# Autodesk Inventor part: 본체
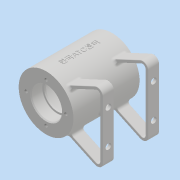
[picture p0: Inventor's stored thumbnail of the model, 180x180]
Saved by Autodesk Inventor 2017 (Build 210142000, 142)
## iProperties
Part Number: 본체
Material: 일반
Document SubType Name: Modeling
Designer: Administrator
Density: 1 g/cm^3
Appearance: 기본값
Author: Administrator
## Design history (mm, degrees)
sketch "스케치1"
  geometry: C1 r 29 at (0, 0); 1 further point
  constraints: 1 centre point, 1 coincident
  dimensions: "d0" = 58 diameter of C1
extrude "돌출1" new body sketch "스케치1" distance "d1" = 35; taper "d3" = 0 deg; dims "d2" = 35, "d4" = 0
sketch "스케치2"
  geometry: C1 r 21 at (0, 0); 1 further point
  constraints: 1 centre point, 1 coincident
  dimensions: "d5" = 42 diameter of C1
extrude "돌출2" cut sketch "스케치2" distance "d6" = 21; taper "d8" = 0 deg; dims "d7" = 21, "d9" = 0
sketch "스케치3"
  geometry: C1 r 14 at (0, 0); 1 further point
  constraints: 1 centre point, 1 coincident
  dimensions: "d10" = 28 diameter of C1
extrude "돌출3" cut sketch "스케치3" distance "d11" = 23; taper "d13" = 0 deg; dims "d12" = 23, "d14" = 0
sketch "스케치4"
  geometry: C1 r 14 at (0, 0) reference; C2 r 16 at (0, 0); 1 further point
  constraints: 1 centre point, 1 coincident
  dimensions: "d15" = 32 diameter of C2
extrude "돌출4" cut sketch "스케치4" distance "d16" = 12; taper "d17" = 0 deg
sketch "스케치5"
  geometry: C1 r 16 at (0, 0); 1 further point
  constraints: 1 centre point, 1 coincident
  dimensions: "d18" = 32 diameter of C1
extrude "돌출5" cut sketch "스케치5" distance "d19" = 12; taper "d20" = 0 deg
sketch "스케치6"
  geometry: 2 further points
  constraints: 1 horizontal alignment
  dimensions: "d21" = 21 distance of point (0, 0) point (-21, 0)
hole "구멍1" sketch "스케치6" at (-21, 0) diameter "d22" = 3.242; stored, may be unused: countersink angle "d26" = 90 deg, drill point angle "d28" = 118 deg; dims "d23" = 8, "d24" = 4, "d25" = 2, "d27" = 10
sketch "스케치7"
  geometry: 2 further points
  constraints: 1 horizontal alignment
  dimensions: "d32" = 21 distance of point (0, 0) point (-21, 0)
hole "구멍2" sketch "스케치7" at (-21, 0) diameter "d33" = 3.242; stored, may be unused: countersink angle "d37" = 90 deg, drill point angle "d39" = 118 deg; dims "d34" = 8, "d35" = 4, "d36" = 2, "d38" = 10
sketch "스케치8"
  geometry: L1 (0, 0)-(-30.07, -10.945); L2 (0, 0)-(32, 0); L3 (-30.07, -10.945)-(-28.018, -16.583); L4 (-23.397, -8.516)-(-21.345, -14.154); L5 (-21.345, -14.154)-(-28.018, -16.583)
  constraints: 10 end point, 2 perpendicular, 1 equal length, 1 horizontal, 1 parallel, 1 point on line
  dimensions: "d43" = 160 deg angle of L1 L2; "d45" = 32 distance of L1.start L1.end; "d46" = 6 distance of L1.end L3.end; "d47" = 6.67327 horizontal distance of L4.end L3.end
revolve "회전1" sketch "스케치8" stored, may be unused: angle "d48" = 90 deg
sketch "스케치9"
  geometry: 2 further points
  constraints: 2 coincident
hole "구멍3" sketch "스케치9" at (0, 0) diameter "d49" = 5.188; stored, may be unused: countersink angle "d53" = 90 deg, drill point angle "d55" = 118 deg; dims "d50" = 20, "d51" = 4, "d52" = 2, "d54" = 29
node "작업 평면1"
sketch "스케치12"
  geometry: C1 r 5 at (0, 0); 1 further point
  constraints: 1 centre point, 1 coincident
  dimensions: "d59" = 10 diameter of C1
extrude "돌출6" join sketch "스케치12" stored distance "d60" = 10; taper "d61" = 0 deg
node "작업 평면2"
sketch "스케치13"
  geometry: L1 (-55, 30.582)-(-55, -30.582); L2 (0, 0)-(0, -50.41); L3 (-46.464, -36.02)-(-17.993, -22.743); L4 (-55, -40)-(-23.585, -40); L5 (-46.464, 36.02)-(-17.993, 22.743); L6 (-55, 40)-(-23.585, 40); L7 (-20.438, 20.574)-(-47.732, 33.301); L8 (-52, 30.582)-(-52, -30.582); L9 (-47.732, -33.301)-(-20.438, -20.574); A1 r 29 centre (0, 0) between (-17.993, 22.743) and (-17.993, -22.743) reference; A2 r 6 centre (-49, -30.582) between (-55, -30.582) and (-46.464, -36.02); A3 r 6 centre (-49, 30.582) between (-46.464, 36.02) and (-55, 30.582); A4 r 3 centre (-49, 30.582) between (-47.732, 33.301) and (-52, 30.582); A5 r 3 centre (-49, -30.582) between (-52, -30.582) and (-47.732, -33.301); 2 further points
  constraints: 18 end point, 12 point on circle, 4 centre point, 4 point on line, 4 tangent, 2 equal length, 2 horizontal, 1 equal radius, 1 horizontal alignment, 1 midpoint, 1 parallel, 1 vertical, 2 other
  dimensions: "d63" = 55 distance from line of L1 point (0, 0); "d64" = 80 distance of L6.start L4.start; "d65" = 25 deg angle of L4 L3; "d66" = 25 deg angle of L5 L6; "d67" = 50.40972 distance of L2.start L2.end; "d71" = 6 radius of A2; "d72" = 3 distance between parallel lines of L5 L7; "d73" = 3 distance between parallel lines of L1 L8; "d74" = 3 distance between parallel lines of L3 L9
extrude "돌출7" join sketch "스케치13" distance "d75" = 12; taper "d76" = 0 deg
sketch "스케치14"
  geometry: L1 (0, 0)-(61.164, 0) reference; L2 (61.164, 0)-(61.164, 12) reference; L3 (0, 12)-(61.164, 12) reference; L4 (0, 0)-(0, 12) reference; C1 r 3 at (48.582, 6); C2 r 3 at (12.582, 6); 1 further point
  constraints: 2 centre point
  dimensions: "d77" = 6 diameter of C1; "d78" = 6 diameter of C2; "d80" = 6 distance from line of L3 C1.centre; "d81" = 6 distance from line of L3 C2.centre; "d82" = 36 distance of C2.centre C1.centre; "d83" = 18 horizontal distance of point (30.582, -18) C1.centre
extrude "돌출8" cut sketch "스케치14" distance "d84" = 12; taper "d85" = 0 deg
sketch "스케치15"
  geometry: 2 further points
  constraints: 1 coincident
hole "구멍4" sketch "스케치15" at (0, 0) diameter "d86" = 5.188; stored, may be unused: countersink angle "d90" = 90 deg, drill point angle "d92" = 118 deg; dims "d87" = 6, "d88" = 4, "d89" = 2, "d91" = 8
sketch "스케치16"
  geometry: C1 r 1.5 at (0, 0); 1 further point
  constraints: 1 centre point, 1 coincident
  dimensions: "d93" = 3 diameter of C1
extrude "돌출9" cut sketch "스케치16" distance "d94" = 34.75; taper "d95" = 0 deg
fillet "모깎기1" dims "d96" = 1
fillet "모깎기2" dims "d97" = 0.5
fillet "모깎기3" dims "d98" = 0.5
fillet "모깎기4" dims "d99" = 0.3
fillet "모깎기5" dims "d100" = 3
fillet "모깎기6" dims "d101" = 3
chamfer "모따기1" distance "d102" = 1; stored, may be unused: second distance "d103" = 2, angle "d104" = 45 deg
node "작업 평면4"
sketch "스케치18"
  geometry: L1 (-29, -35)-(29, -35) reference; L2 (-29, -35)-(-29, 35) reference; 2 further points
  constraints: 1 other
  dimensions: "d111" = 35 distance from line of L1 point (0, 0); "d112" = 29 distance from line of L2 point (0, 0)
feature "엠보싱2" sketch "스케치18" dims "d113" = 0.5, "d114" = 0
node "솔리드1"
pattern_circular "원형 패턴1" dims angle "d30" = 360 deg
pattern_circular "원형 패턴2" dims angle "d41" = 360 deg
mirror "미러1"
node "투영된 루프1"
other parameters: "d58" = -32, "d62" = 18, "d110" = 29
